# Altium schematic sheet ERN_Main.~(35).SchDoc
size A; SheetNumber: 1; SheetTotal: 1; SPICEModelCacheDBTNACQE: <root> / <DocumentId>DBTNACQE</DocumentId> / <CacheFrame Number="0"> / <Model Name="1n5400" Kind="MDL"> / <Text>*1N5400 MCE / * 50V 3A Si Rectifier pkg:DO-201 1,2 / .MODEL 1N5400 D(IS=2.68E-12 RS=0.00977 N=1.17 TT=1.44E-5 CJO=1.24E-10 / + VJ=0.6 M=0.333 BV=66.6 IBV=1E-5 )</Text> / </Model> / <Model Name="led2" Kind="MDL"> / <Text>*Typ RED,GREEN,YELLOW,AMBER GaAs LED: Vf=2.1V Vr=4V If=40mA trr=3uS / *LED Pinout: 1=A, 2=K / .MODEL LED2 D (IS=93.1P RS=42M N=4.61 BV=4 IBV=10U / + CJO=2.97P VJ=.75 M=.333 TT=4.32U)</Text> / </Model> / <Model Name="irf1010" Kind="CKT"> / <Text>*IRF1010 MCE 4-2-96 / *55V  75A .014 ohm HEXFET pkg:TO-220 2,1,3 / .SUBCKT IRF1010  10 20 40 40 / M1   1  2  3  3  DMOS L=1U W=1U / RD  10  1  5.65M / RS  30  3  1.35M / RG  20  2  12.1 / CGS  2  3  2.15N / EGD 12  0  2  1  1 / VFB 14  0  0 / FFB  2  1  VFB  1 / CGD 13 14  4.49N / R1  13  0  1 / D1  12 13  DLIM / DDG 15 14  DCGD / R2  12 15  1 / D2  15  0  DLIM / DSD  3 10  DSUB / LS  30 40  7.5N / .MODEL DMOS NMOS (LEVEL=3 THETA=60M VMAX=114K ETA=2M VTO=3 KP=19.4) / .MODEL DCGD D (CJO=4.49N VJ=.6 M=.68) / .MODEL DSUB D (IS=311N N=1.5 RS=8.67M BV=55 CJO=4.08N VJ=.8 M=.42 TT=100N) / .MODEL DLIM D (IS=100U) / .ENDS IRF1010</Text> / </Model> / </CacheFrame> / </root>
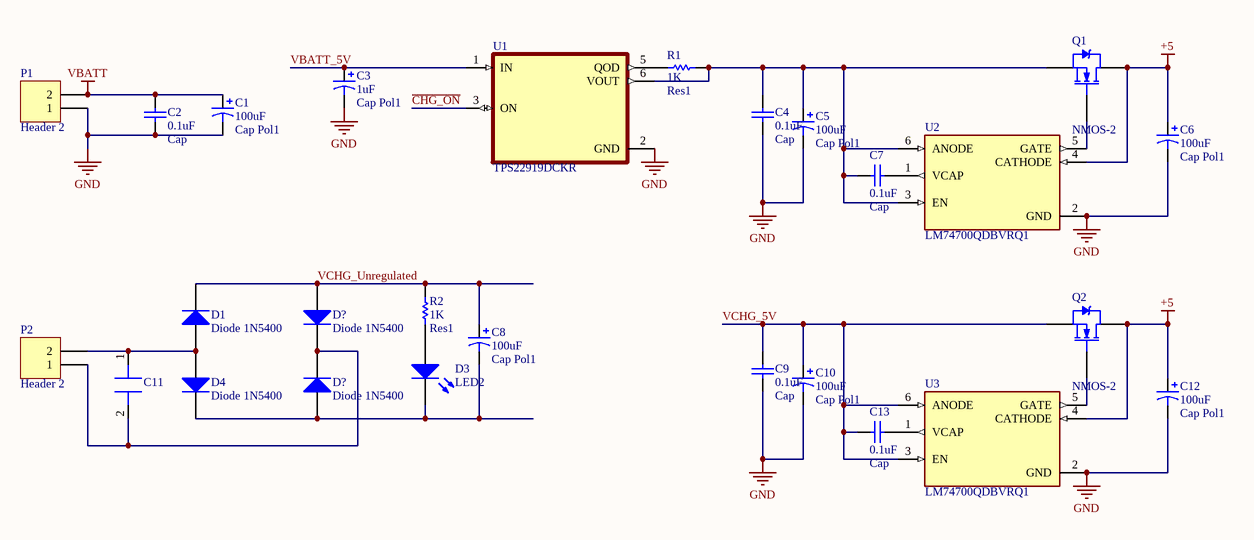
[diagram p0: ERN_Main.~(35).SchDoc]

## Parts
(Parts that share a designator on the sheet are numbered #1, #2 ... from top to bottom, then left to right.)
C1  Cap Pol1  value 100uF  [RB7.6-15]
C2  Cap  value 0.1uF  [RAD-0.3]
C3  Cap Pol1  value 1uF  [RB7.6-15]
C4  Cap  value 0.1uF  [RAD-0.3]
C5  Cap Pol1  value 100uF  [RB7.6-15]
C6  Cap Pol1  value 100uF  [RB7.6-15]
C7  Cap  value 0.1uF  [RAD-0.3]
C8  Cap Pol1  value 100uF  [RB7.6-15]
C9  Cap  value 0.1uF  [RAD-0.3]
C10  Cap Pol1  value 100uF  [RB7.6-15]
C11  C2220C944K5GLCAUTO  [CAPC5750X39M]  (value not drawn)
C12  Cap Pol1  value 100uF  [RB7.6-15]
C13  Cap  value 0.1uF  [RAD-0.3]
D1  Diode 1N5400  [DO-201AD]
D3  LED2  [3.2X1.6X1.1]
D4  Diode 1N5400  [DO-201AD]
D?#1  Diode 1N5400  [DO-201AD]
D?#2  Diode 1N5400  [DO-201AD]
P1  Header 2  [HDR1X2]
P2  Header 2  [HDR1X2]
Q1  NMOS-2  [TO-220AB]
Q2  NMOS-2  [TO-220AB]
R1  Res1  value 1K  [AXIAL-0.3]
R2  Res1  value 1K  [AXIAL-0.3]
U1  TPS22919DCKR  [SOT65P210X110-6N]
U2  LM74700QDBVRQ1  [SOT95P280X145-6N]
U3  LM74700QDBVRQ1  [SOT95P280X145-6N]

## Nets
+5: C6.1 C12.1 Q1.2(D) Q2.2(D) U2.4(CATHODE) U3.4(CATHODE)
GND: C1.2 C2.1 C3.2 C4.1 C5.2 C6.2 C9.1 C10.2 C12.2 P1.1 U1.2(GND) U2.2(GND) U3.2(GND)
VBATT: C1.1 C2.2 P1.2
~{CHG_ON}: U1.3(ON)
VBATT_5V: C3.1 U1.1(IN)
VCHG_5V: C9.2 C10.1 C13.2 Q2.3(S) U3.3(EN) U3.6(ANODE)
VCHG_Unregulated: C8.1 D1.2(K) D?#1.1(A) R2.2
NetC4_2: C4.2 C5.1 C7.2 Q1.3(S) R1.1 U1.6(VOUT) U2.3(EN) U2.6(ANODE)
NetC7_1: C7.1 U2.1(VCAP)
NetC8_2: C8.2 D3.2(K) D4.2(K) D?#2.1(A)
NetC11_1: C11.1 D1.1(A) D4.1(A) P2.2
NetC11_2: C11.2 D?#1.2(K) D?#2.2(K) P2.1
NetC13_1: C13.1 U3.1(VCAP)
NetD3_1: D3.1(A) R2.1
NetQ1_1: Q1.1(G) U2.5(GATE)
NetQ2_1: Q2.1(G) U3.5(GATE)
NetR1_2: R1.2 U1.5(QOD)

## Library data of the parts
C1 C3 C5 C6 C8 C10 C12 = Cap Pol1: Polarized Capacitor (Radial)
C2 C4 C7 C9 C13 = Cap: Capacitor
C11 = C2220C944K5GLCAUTO: CAP CER 0.94UF 50V C0G/NP0 2220
D1 D4 D?#1 D?#2 = Diode 1N5400: 3 Amp General Purpose Rectifier
D3 = LED2: Typical RED, GREEN, YELLOW, AMBER GaAs LED
P1 P2 = Header 2: Header, 2-Pin
Q1 Q2 = NMOS-2: N-Channel Power MOSFET; Note: Pin 2 is electrically connected to pin 4.
R1 R2 = Res1: Resistor
U1 = TPS22919DCKR: 5.5-V, 1.5-A, 90-mÎ© load switch with adj. output discharge; MF: Texas Instruments
U2 U3 = LM74700QDBVRQ1: 3.2-V to 65-V, 80-uA IQ automotive ideal diode controller; MF: Texas Instruments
